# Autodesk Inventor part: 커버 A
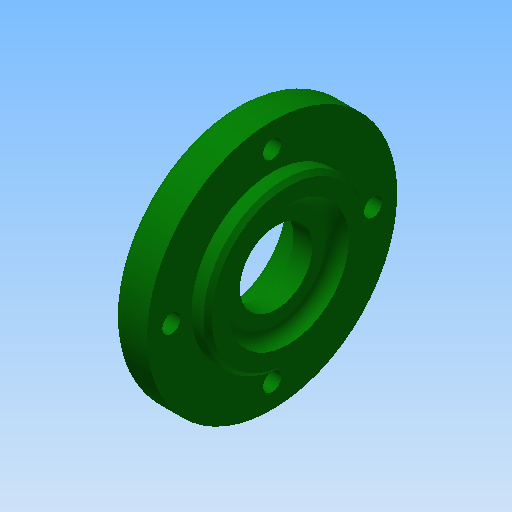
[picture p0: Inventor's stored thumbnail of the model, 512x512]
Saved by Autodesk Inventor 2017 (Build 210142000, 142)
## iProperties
Created: 2019-01
Part Number: 커버 A
Material: 알루미늄 6061
Document SubType Name: Modeling
Designer: mduedu
Density: 2.71 g/cm^3
Appearance: 진녹색
Mass: 67.6019 g
Surface Area: 94.4617 cm^2
Volume: 24.9453 cm^3
Author: mduedu
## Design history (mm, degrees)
sketch "스케치1"
  geometry: L1 (0, 0)-(9, 0); L2 (9, 0)-(9, 31); L3 (9, 31)-(0, 31); L4 (0, 31)-(0, 0); L5 (9, 0)-(13, 0); L6 (13, 0)-(13, 20); L7 (13, 20)-(9, 20); L8 (9, 20)-(9, 0)
  constraints: 16 end point, 4 parallel, 2 horizontal, 2 perpendicular
  dimensions: "d0" = 13 distance between parallel lines of L6 L4; "d2" = 62 diameter of L3 L1; "d3" = 40 diameter of L7 L5; "d4" = 4 distance between parallel lines of L6 L2
revolve "회전1" sketch "스케치1" stored, may be unused: angle "d5" = 90 deg
sketch "스케치5"
  geometry: C1 r 19 at (0, 0); 1 further point
  constraints: 1 centre point, 1 coincident
  dimensions: "d34" = 38 diameter of C1
extrude "돌출1" join sketch "스케치5" distance "d35" = 3; taper "d36" = 0 deg
sketch "스케치2"
  geometry: L1 (9, -20)-(9, -31) reference; L2 (9, -31)-(0, -31) reference; L3 (0, -31)-(0, -19) reference; L4 (0, -19)-(-3, -19) reference; L5 (-3, -19)-(-3, 19) reference; L6 (-3, 19)-(0, 19) reference; L7 (0, 19)-(0, 31) reference; L8 (0, 31)-(9, 31) reference; L9 (9, 31)-(9, 20) reference; L10 (9, 20)-(13, 20) reference; L11 (13, 20)-(13, -20) reference; L12 (13, -20)-(9, -20) reference; L13 (-3, 0)-(5.3, 0); L14 (5.3, 0)-(5.3, 15); L15 (5.3, 15)-(-3, 15); L16 (-3, 15)-(-3, 0); L17 (5.3, 0)-(10, 0); L18 (10, 0)-(10, 9); L19 (10, 9)-(5.3, 9); L20 (5.3, 9)-(5.3, 0); L21 (10, 0)-(13, 0); L22 (13, 0)-(13, 15); L23 (13, 15)-(10, 15); L24 (10, 15)-(10, 0)
  constraints: 24 end point, 6 parallel, 3 horizontal, 3 perpendicular, 1 midpoint, 1 point on line
  dimensions: "d38" = 30 diameter of L15 L13; "d40" = 30 diameter of L23 L21; "d41" = 3 distance of L22.end L23.end; "d42" = 8.3 distance of L14.end L15.end; "d43" = 18 diameter of L19 L17
revolve "회전2" sketch "스케치2" stored, may be unused: angle "d12" = 90 deg
chamfer "모따기1" distance "d13" = 0.8; stored, may be unused: second distance "d14" = 2, angle "d15" = 30 deg
fillet "모깎기1" dims "d16" = 0.5
fillet "모깎기2" dims "d17" = 3
fillet "모깎기3" dims "d18" = 3
chamfer "모따기2" distance "d24" = 1; stored, may be unused: second distance "d25" = 2, angle "d26" = 45 deg
sketch "스케치3" dims "d19" = 50
  geometry: 6 further points
  constraints: 2 vertical alignment, 1 coincident, 7 other
  dimensions: "d22" = 360 deg dimension on point (0, 0) point (0, 25) (derived)
sketch "스케치4"
  geometry: 4 further points
  constraints: 4 other
hole "구멍1" sketch "스케치4" at (-25, 0), (0, -25), (25, 0), (0, 25) diameter "d27" = 4.5; stored, may be unused: countersink angle "d31" = 90 deg, drill point angle "d33" = 0 deg; dims "d28" = 6, "d29" = 8, "d30" = 4.6, "d32" = 8
fillet "모깎기6" dims "d47" = 1
node "솔리드1"
node "절단 모서리 투영2"
